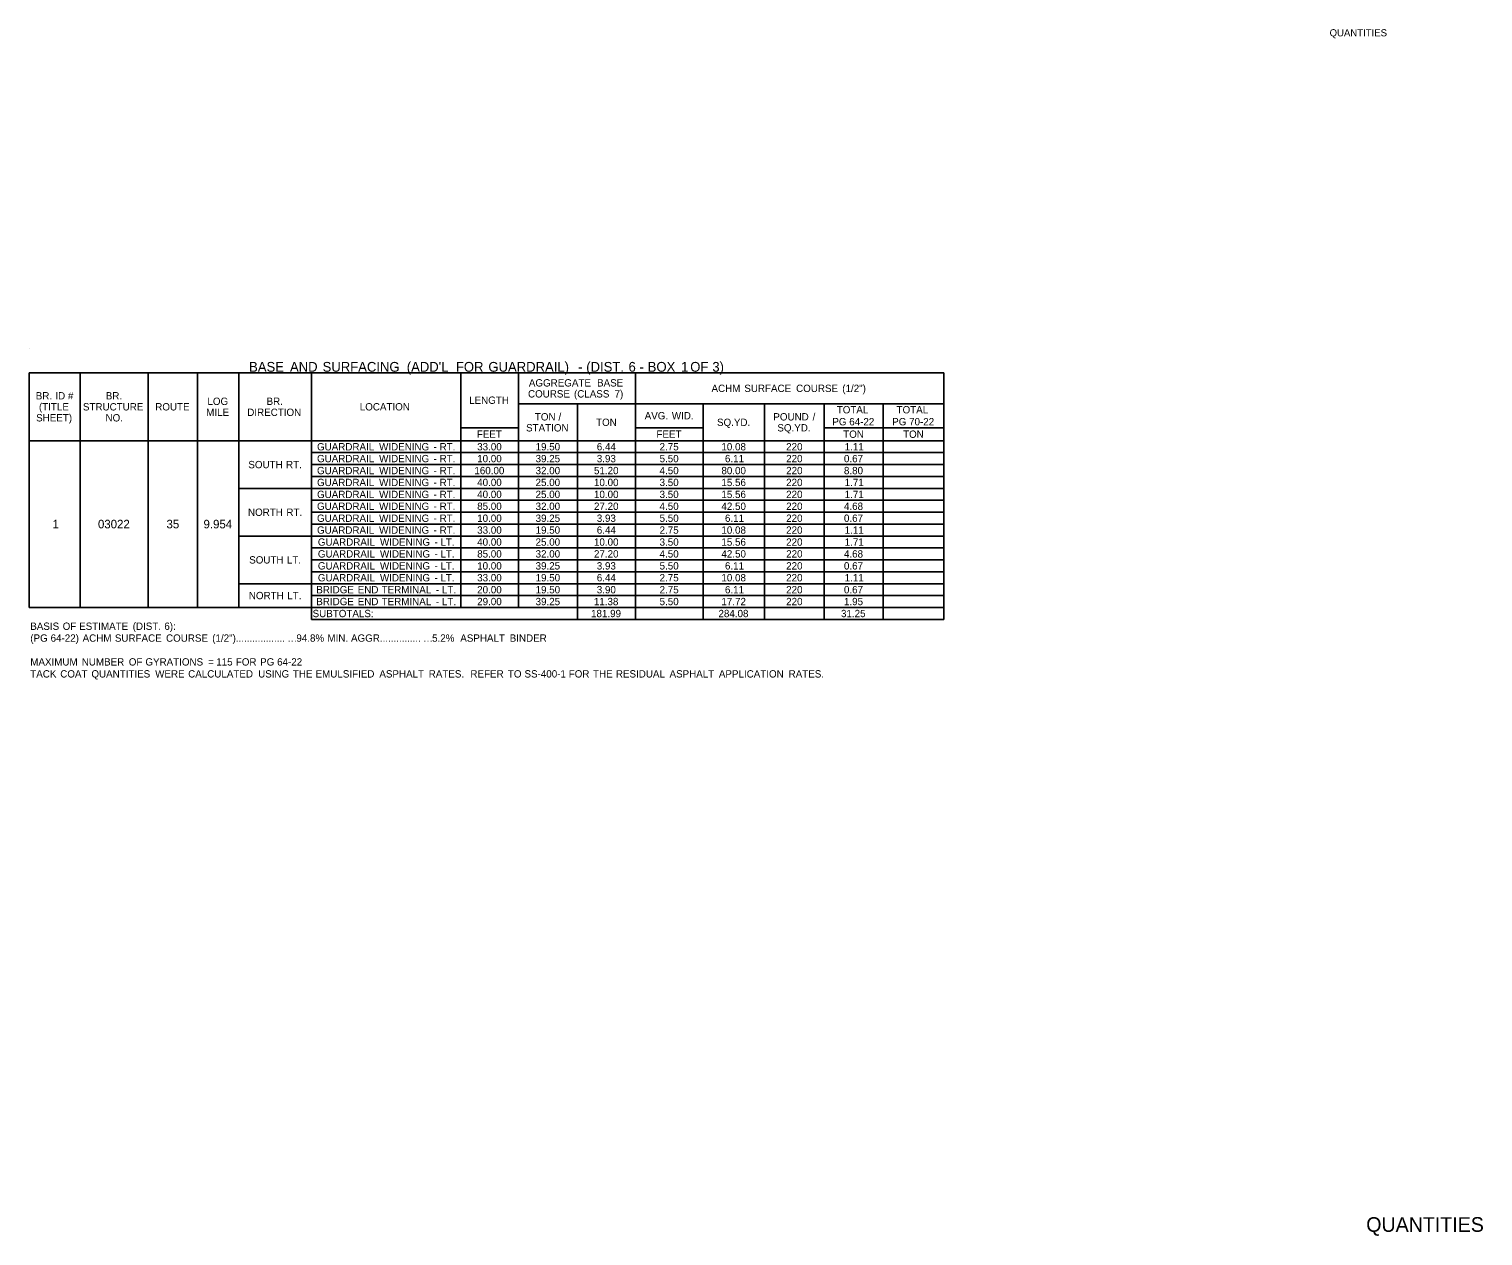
# Model space of a CAD drawing. Extents: x 542596 to 1930787, y -1948294 to 596640.
# Drawn here: x 550299 to 551489, y -1947044 to -1946056 of the extents above; entities that cross this region are included whole.
import ezdxf

# ---------------------------------------------------------------- set-up
doc = ezdxf.new("R2010")
doc.units = 0
for name, color, linetype in [('Default', 7, 'Continuous'), ('R_Border', 7, 'Continuous'), ('R_Border Prem', 7, 'Continuous')]:
    doc.layers.add(name, color=color, linetype=linetype)

msp = doc.modelspace()

# ---------------------------------------------------------------- linework, layer by layer
at = {"layer": 'Default'}
for p, q in [((550298.7, -1946318.3), (550298.7, -1946318.3)), ((550298.7, -1946337.8), (551047.5, -1946337.8)), ((550298.7, -1946529.9), (550298.7, -1946337.8)), ((550340.6, -1946393.4), (550340.6, -1946337.8)), ((550396.2, -1946393.4), (550396.2, -1946337.8)), ((550436.7, -1946393.4), (550436.7, -1946337.8)), ((550470.3, -1946529.9), (550470.3, -1946337.8)), ((550529.8, -1946539.6), (550529.8, -1946337.8)), ((550652.2, -1946529.9), (550652.2, -1946337.8)), ((550699.4, -1946529.9), (550699.4, -1946337.8)), ((550795, -1946539.6), (550795, -1946337.8)), ((551047.5, -1946539.6), (551047.5, -1946337.8)), ((550699.4, -1946363.2), (551047.5, -1946363.2)), ((550747.7, -1946539.6), (550747.7, -1946363.2)), ((550850.6, -1946363.2), (550900.8, -1946363.2)), ((550850.6, -1946539.6), (550850.6, -1946363.2)), ((550900.8, -1946539.6), (550900.8, -1946363.2)), ((550949.5, -1946539.6), (550949.5, -1946363.2)), ((550997.8, -1946539.6), (550997.8, -1946363.2)), ((550652.2, -1946382.7), (550699.4, -1946382.7)), ((550699.4, -1946529.9), (550699.4, -1946382.7)), ((550795, -1946382.7), (550850.6, -1946382.7)), ((550795, -1946393.4), (550795, -1946382.7)), ((550850.6, -1946539.6), (550850.6, -1946382.7)), ((550949.5, -1946382.7), (551047.5, -1946382.7)), ((550298.7, -1946393.4), (550949.5, -1946393.4)), ((550340.6, -1946529.9), (550340.6, -1946393.4)), ((550396.2, -1946529.9), (550396.2, -1946393.4)), ((550436.7, -1946529.9), (550436.7, -1946393.4)), ((550652.2, -1946461.6), (550652.2, -1946393.4)), ((550699.4, -1946393.4), (550850.6, -1946393.4)), ((550747.7, -1946539.6), (550747.7, -1946393.4)), ((550850.6, -1946393.4), (551047.5, -1946393.4)), ((550900.8, -1946529.9), (550900.8, -1946393.4)), ((550529.8, -1946403.1), (551047.5, -1946403.1)), ((550529.8, -1946412.9), (551047.5, -1946412.9)), ((550529.8, -1946422.6), (551047.5, -1946422.6)), ((550470.3, -1946432.4), (551047.5, -1946432.4)), ((550470.3, -1946432.4), (550529.8, -1946432.4)), ((550529.8, -1946442.1), (551047.5, -1946442.1)), ((550529.8, -1946451.9), (551047.5, -1946451.9)), ((550529.8, -1946461.6), (551047.5, -1946461.6)), ((550470.3, -1946471.4), (551047.5, -1946471.4)), ((550470.3, -1946471.4), (550529.8, -1946471.4)), ((550652.2, -1946510.4), (550652.2, -1946471.4)), ((550529.8, -1946481.1), (551047.5, -1946481.1)), ((550529.8, -1946490.9), (551047.5, -1946490.9)), ((550529.8, -1946500.6), (551047.5, -1946500.6)), ((550470.3, -1946510.4), (551047.5, -1946510.4)), ((550470.3, -1946510.4), (550529.8, -1946510.4)), ((550529.8, -1946520.1), (551047.5, -1946520.1)), ((550298.7, -1946529.9), (551047.5, -1946529.9)), ((550529.8, -1946529.9), (551047.5, -1946529.9)), ((550529.8, -1946539.6), (550529.8, -1946529.9)), ((550795, -1946539.6), (550795, -1946529.9)), ((550949.5, -1946539.6), (550949.5, -1946529.9)), ((550529.8, -1946539.6), (551047.5, -1946539.6))]:
    msp.add_line(p, q, dxfattribs=at)

# ---------------------------------------------------------------- texts
for s, height, p in [('BASE', 8, (550478.8, -1946336.9)), (' AND', 8, (550509.3, -1946336.9)), (' SURFACING', 8, (550536, -1946336.9)), (" (ADD'L", 8, (550604.9, -1946336.9)), (' FOR', 8, (550645.1, -1946336.9)), (' GUARDRAIL)', 8, (550671.7, -1946336.9)), (' -', 8, (550745.1, -1946336.9)), (' (DIST.', 8, (550751.8, -1946336.9)), (' 6', 8, (550786.4, -1946336.9)), (' -', 8, (550795.3, -1946336.9)), (' BOX', 8, (550802.1, -1946336.9)), (' 1', 8, (550829.4, -1946336.9)), (' OF', 8, (550836.9, -1946336.9)), (' 3)', 8, (550855, -1946336.9)), ('AGGREGATE', 6, (550707.8, -1946349)), (' BASE', 6, (550761.4, -1946349)), ('ACHM', 6, (550857.3, -1946353.5)), (' SURFACE', 6, (550881.9, -1946353.5)), (' COURSE', 6, (550924.3, -1946353.5)), (' (1/2")', 6, (550962.1, -1946353.5)), ('BR.', 6, (550304.2, -1946359.6)), (' ID', 6, (550318, -1946359.6)), (' #', 6, (550328.3, -1946359.6)), ('BR.', 6, (550361.5, -1946359.6)), ('LOG', 6, (550444.7, -1946364.1)), ('BR.', 6, (550493.1, -1946364.1)), ('LENGTH', 6, (550658.9, -1946363.2)), ('COURSE', 6, (550707.1, -1946358)), (' (CLASS', 6, (550742.5, -1946358)), (' 7)', 6, (550775.7, -1946358)), ('SHEET)', 6, (550304.5, -1946377.6)), ('(TITLE', 6, (550306.8, -1946368.6)), ('STRUCTURE', 6, (550342.8, -1946368.6)), ('NO.', 6, (550361.3, -1946377.6)), ('ROUTE', 6, (550402, -1946368.6)), ('MILE', 6, (550443.7, -1946373.1)), ('DIRECTION', 6, (550477.3, -1946373.1)), ('LOCATION', 6, (550569.4, -1946368.6)), ('TON', 6, (550712.7, -1946376.8)), (' /', 6, (550729.8, -1946376.8)), ('AVG.', 6, (550802.6, -1946375.9)), (' WID.', 6, (550822.6, -1946375.9)), ('POUND', 6, (550907.9, -1946376.8)), (' /', 6, (550937.8, -1946376.8)), ('TOTAL', 6, (550959.8, -1946371)), ('TOTAL', 6, (551008.8, -1946371)), ('STATION', 6, (550705.5, -1946385.8)), ('TON', 6, (550762.8, -1946381.3)), ('SQ.YD.', 6, (550861.8, -1946381.3)), ('SQ.YD.', 6, (550911.2, -1946385.8)), ('PG', 6, (550956.2, -1946380.8)), (' 64-22', 6, (550967.8, -1946380.8)), ('PG', 6, (551005.2, -1946380.8)), (' 70-22', 6, (551016.8, -1946380.8)), ('GUARDRAIL', 6, (550534.4, -1946401.3)), (' WIDENING', 6, (550583, -1946401.3)), (' RT.', 6, (550632.5, -1946401.3)), ('FEET', 6, (550665.2, -1946391)), ('33.00', 6, (550665.5, -1946401.3)), ('19.50', 6, (550713.3, -1946401.3)), ('6.44', 6, (550763.4, -1946401.3)), ('FEET', 6, (550812.2, -1946391)), ('2.75', 6, (550814.8, -1946401.3)), ('10.08', 6, (550865.4, -1946401.3)), ('220', 6, (550918.4, -1946401.3)), ('TON', 6, (550965.1, -1946391)), ('1.11', 6, (550966.3, -1946401.3)), ('TON', 6, (551014.1, -1946391)), ('GUARDRAIL', 6, (550534.4, -1946411)), (' WIDENING', 6, (550583, -1946411)), (' -', 6, (550627.6, -1946401.3)), (' RT.', 6, (550632.5, -1946411)), ('10.00', 6, (550665.5, -1946411)), ('39.25', 6, (550713.3, -1946411)), ('3.93', 6, (550763.4, -1946411)), ('5.50', 6, (550814.8, -1946411)), ('6.11', 6, (550868.3, -1946411)), ('220', 6, (550918.4, -1946411)), ('0.67', 6, (550965.7, -1946411)), ('SOUTH', 6, (550478.2, -1946415.9)), (' RT.', 6, (550506.8, -1946415.9)), ('GUARDRAIL', 6, (550534.4, -1946420.8)), (' WIDENING', 6, (550583, -1946420.8)), (' -', 6, (550627.6, -1946411)), (' -', 6, (550627.6, -1946420.8)), (' RT.', 6, (550632.5, -1946420.8)), ('160.00', 6, (550663.2, -1946420.8)), ('32.00', 6, (550713.3, -1946420.8)), ('51.20', 6, (550761.1, -1946420.8)), ('4.50', 6, (550814.8, -1946420.8)), ('80.00', 6, (550865.4, -1946420.8)), ('220', 6, (550918.4, -1946420.8)), ('8.80', 6, (550965.7, -1946420.8)), ('GUARDRAIL', 6, (550534.4, -1946430.5)), (' WIDENING', 6, (550583, -1946430.5)), (' -', 6, (550627.6, -1946430.5)), (' RT.', 6, (550632.5, -1946430.5)), ('40.00', 6, (550665.5, -1946430.5)), ('25.00', 6, (550713.3, -1946430.5)), ('10.00', 6, (550761.1, -1946430.5)), ('3.50', 6, (550814.8, -1946430.5)), ('15.56', 6, (550865.4, -1946430.5)), ('220', 6, (550918.4, -1946430.5)), ('1.71', 6, (550966.3, -1946430.5)), ('GUARDRAIL', 6, (550534.4, -1946440.3)), ('GUARDRAIL', 6, (550534.4, -1946450)), (' WIDENING', 6, (550583, -1946440.3)), (' WIDENING', 6, (550583, -1946450)), (' -', 6, (550627.6, -1946440.3)), (' RT.', 6, (550632.5, -1946440.3)), (' RT.', 6, (550632.5, -1946450)), ('40.00', 6, (550665.5, -1946440.3)), ('85.00', 6, (550665.5, -1946450)), ('32.00', 6, (550713.3, -1946450)), ('25.00', 6, (550713.3, -1946440.3)), ('27.20', 6, (550761.1, -1946450)), ('10.00', 6, (550761.1, -1946440.3)), ('4.50', 6, (550814.8, -1946450)), ('3.50', 6, (550814.8, -1946440.3)), ('42.50', 6, (550865.4, -1946450)), ('15.56', 6, (550865.4, -1946440.3)), ('220', 6, (550918.4, -1946440.3)), ('220', 6, (550918.4, -1946450)), ('4.68', 6, (550965.7, -1946450)), ('1.71', 6, (550966.3, -1946440.3)), ('NORTH', 6, (550477.9, -1946454.9)), (' RT.', 6, (550507.1, -1946454.9)), ('GUARDRAIL', 6, (550534.4, -1946459.8)), (' WIDENING', 6, (550583, -1946459.8)), (' -', 6, (550627.6, -1946450)), (' RT.', 6, (550632.5, -1946459.8)), ('10.00', 6, (550665.5, -1946459.8)), ('39.25', 6, (550713.3, -1946459.8)), ('3.93', 6, (550763.4, -1946459.8)), ('5.50', 6, (550814.8, -1946459.8)), ('6.11', 6, (550868.3, -1946459.8)), ('220', 6, (550918.4, -1946459.8)), ('0.67', 6, (550965.7, -1946459.8)), ('1', 7, (550317.9, -1946465.1)), ('03022', 7, (550355.1, -1946465.1)), ('35', 7, (550411.2, -1946465.1)), ('9.954', 7, (550441.5, -1946465.1)), ('GUARDRAIL', 6, (550534.4, -1946469.5)), (' WIDENING', 6, (550583, -1946469.5)), (' -', 6, (550627.6, -1946459.8)), (' -', 6, (550627.6, -1946469.5)), (' RT.', 6, (550632.5, -1946469.5)), ('33.00', 6, (550665.5, -1946469.5)), ('19.50', 6, (550713.3, -1946469.5)), ('6.44', 6, (550763.4, -1946469.5)), ('2.75', 6, (550814.8, -1946469.5)), ('10.08', 6, (550865.4, -1946469.5)), ('220', 6, (550918.4, -1946469.5)), ('1.11', 6, (550966.3, -1946469.5)), ('GUARDRAIL', 6, (550535.1, -1946479.3)), (' WIDENING', 6, (550583.7, -1946479.3)), (' -', 6, (550628.3, -1946479.3)), (' LT.', 6, (550633.2, -1946479.3)), ('40.00', 6, (550665.5, -1946479.3)), ('25.00', 6, (550713.3, -1946479.3)), ('10.00', 6, (550761.1, -1946479.3)), ('3.50', 6, (550814.8, -1946479.3)), ('15.56', 6, (550865.4, -1946479.3)), ('220', 6, (550918.4, -1946479.3)), ('1.71', 6, (550966.3, -1946479.3)), ('SOUTH', 6, (550478.9, -1946493.9)), (' LT.', 6, (550507.5, -1946493.9)), ('GUARDRAIL', 6, (550535.1, -1946489)), (' WIDENING', 6, (550583.7, -1946489)), (' -', 6, (550628.3, -1946489)), (' LT.', 6, (550633.2, -1946489)), ('85.00', 6, (550665.5, -1946489)), ('32.00', 6, (550713.3, -1946489)), ('27.20', 6, (550761.1, -1946489)), ('4.50', 6, (550814.8, -1946489)), ('42.50', 6, (550865.4, -1946489)), ('220', 6, (550918.4, -1946489)), ('4.68', 6, (550965.7, -1946489)), ('GUARDRAIL', 6, (550535.1, -1946498.8)), ('GUARDRAIL', 6, (550535.1, -1946508.5)), (' WIDENING', 6, (550583.7, -1946498.8)), (' WIDENING', 6, (550583.7, -1946508.5)), (' -', 6, (550628.3, -1946498.8)), (' LT.', 6, (550633.2, -1946498.8)), (' LT.', 6, (550633.2, -1946508.5)), ('33.00', 6, (550665.5, -1946508.5)), ('10.00', 6, (550665.5, -1946498.8)), ('39.25', 6, (550713.3, -1946498.8)), ('19.50', 6, (550713.3, -1946508.5)), ('3.93', 6, (550763.4, -1946498.8)), ('6.44', 6, (550763.4, -1946508.5)), ('5.50', 6, (550814.8, -1946498.8)), ('2.75', 6, (550814.8, -1946508.5)), ('10.08', 6, (550865.4, -1946508.5)), ('6.11', 6, (550868.3, -1946498.8)), ('220', 6, (550918.4, -1946498.8)), ('220', 6, (550918.4, -1946508.5)), ('0.67', 6, (550965.7, -1946498.8)), ('1.11', 6, (550966.3, -1946508.5)), ('BRIDGE', 6, (550533.8, -1946518.3)), (' END', 6, (550565.5, -1946518.3)), (' TERMINAL', 6, (550585.1, -1946518.3)), (' -', 6, (550628.3, -1946508.5)), (' LT.', 6, (550634.4, -1946518.3)), ('20.00', 6, (550665.5, -1946518.3)), ('19.50', 6, (550713.3, -1946518.3)), ('3.90', 6, (550763.4, -1946518.3)), ('2.75', 6, (550814.8, -1946518.3)), ('6.11', 6, (550868.3, -1946518.3)), ('220', 6, (550918.4, -1946518.3)), ('0.67', 6, (550965.7, -1946518.3)), ('NORTH', 6, (550478.6, -1946523.1)), (' LT.', 6, (550507.8, -1946523.1)), ('BRIDGE', 6, (550533.8, -1946528)), (' END', 6, (550565.5, -1946528)), (' TERMINAL', 6, (550585.1, -1946528)), (' -', 6, (550629.5, -1946518.3)), (' -', 6, (550629.5, -1946528)), (' LT.', 6, (550634.4, -1946528)), ('29.00', 6, (550665.5, -1946528)), ('39.25', 6, (550713.3, -1946528)), ('11.38', 6, (550761, -1946528)), ('5.50', 6, (550814.8, -1946528)), ('17.72', 6, (550865.4, -1946528)), ('220', 6, (550918.4, -1946528)), ('1.95', 6, (550965.7, -1946528)), ('SUBTOTALS:', 6, (550530.8, -1946537.8)), ('181.99', 6, (550758.7, -1946537.8)), ('284.08', 6, (550863, -1946537.8)), ('31.25', 6, (550963.3, -1946537.8)), ('BASIS', 6, (550299.7, -1946548.2)), (' OF', 6, (550324, -1946548.2)), (' ESTIMATE', 6, (550337.5, -1946548.2)), (' (DIST.', 6, (550381.3, -1946548.2)), (' 6):', 6, (550407.2, -1946548.2)), ('(PG', 6, (550299.7, -1946557.9)), (' 64-22)', 6, (550314.1, -1946557.9)), (' ACHM', 6, (550340.3, -1946557.9)), (' SURFACE', 6, (550366.7, -1946557.9)), (' COURSE', 6, (550408.6, -1946557.9)), (' (1/2")..................', 6, (550446.4, -1946557.9)), ('…', 6, (550510.1, -1946557.9)), ('94.8%', 6, (550517.5, -1946557.9)), (' MIN.', 6, (550540.7, -1946557.9)), (' AGGR...............', 6, (550560, -1946557.9)), ('…', 6, (550621.2, -1946557.9)), ('5.2%', 6, (550628.6, -1946557.9)), ('  ASPHALT', 6, (550647.2, -1946557.9)), (' BINDER', 6, (550689.9, -1946557.9)), ('MAXIMUM', 6, (550299.7, -1946577.4)), (' NUMBER', 6, (550339.6, -1946577.4)), (' OF', 6, (550378.1, -1946577.4)), (' GYRATIONS', 6, (550391.7, -1946577.4)), (' =', 6, (550443, -1946577.4)), (' 115', 6, (550449.7, -1946577.4)), (' FOR', 6, (550465.7, -1946577.4)), (' PG', 6, (550485.6, -1946577.4)), (' 64-22', 6, (550499.5, -1946577.4)), ('TACK', 6, (550299.7, -1946587.2)), (' COAT', 6, (550322, -1946587.2)), (' QUANTITIES', 6, (550347.5, -1946587.2)), (' WERE', 6, (550399.7, -1946587.2)), (' CALCULATED', 6, (550426.7, -1946587.2)), (' USING', 6, (550484, -1946587.2)), (' THE', 6, (550512.4, -1946587.2)), (' EMULSIFIED', 6, (550531, -1946587.2)), (' ASPHALT', 6, (550583.2, -1946587.2)), (' RATES.', 6, (550623.6, -1946587.2)), ('  REFER', 6, (550655.5, -1946587.2)), (' TO', 6, (550688.4, -1946587.2)), (' SS-400-1', 6, (550702, -1946587.2)), (' FOR', 6, (550738.2, -1946587.2)), (' THE', 6, (550758.1, -1946587.2)), (' RESIDUAL', 6, (550776.8, -1946587.2)), (' ASPHALT', 6, (550820.7, -1946587.2)), (' APPLICATION', 6, (550861.1, -1946587.2)), (' RATES.', 6, (550918.2, -1946587.2))]:
    msp.add_text(s, height=height, dxfattribs=at).set_placement(p)
at = {"layer": 'R_Border'}
msp.add_text('QUANTITIES', height=12, rotation=360, dxfattribs=at).set_placement((551393.2, -1947040.9))
at = {"layer": 'R_Border Prem'}
msp.add_text('QUANTITIES', height=5.86, rotation=360, dxfattribs=at).set_placement((551363.2, -1946062.4))

doc.saveas('drawing.dxf')
